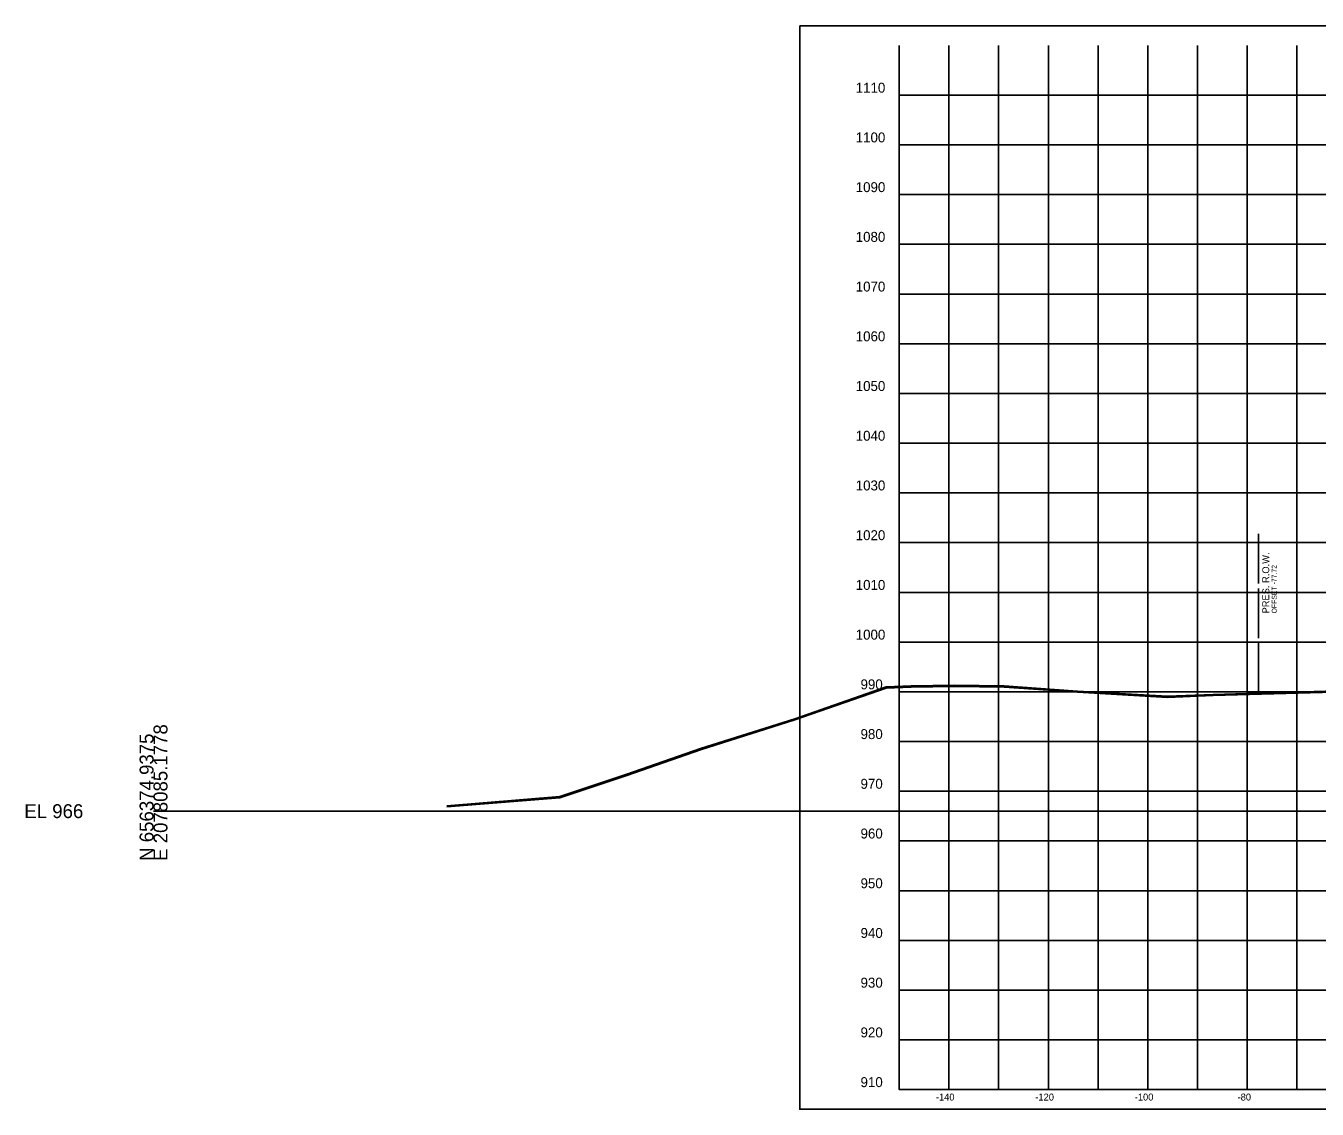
# Model space of a CAD drawing. Extents: x 5868 to 6683, y 2883 to 19120.
# Drawn here: x 5868.1 to 6127.9, y 14385.1 to 14603 of the extents above; entities that cross this region are included whole.
import ezdxf

# ---------------------------------------------------------------- set-up
doc = ezdxf.new("R2010")
doc.units = 0
for name, color, linetype in [('DESIGN - SHEET - Corner Text', 7, 'Continuous'), ('DESIGN - SHEET - Light Grid', 7, 'Continuous'), ('DESIGN - SHEET - Linework', 7, 'Continuous'), ('DESIGN - SHEET - Plot Shape', 7, 'Continuous'), ('SURVEY - GROUND - Bottom of Topsoil Layer', 7, 'Continuous'), ('SURVEY - GROUND - Top of Ground', 7, 'Continuous'), ('SURVEY - PROPERTY - ROW Lines', 7, 'Continuous'), ('SURVEY - PROPERTY - ROW Lines Text', 7, 'Continuous')]:
    doc.layers.add(name, color=color, linetype=linetype)

msp = doc.modelspace()

# ---------------------------------------------------------------- linework, layer by layer
at = {"layer": 'DESIGN - SHEET - Light Grid'}
msp.add_line((5893.78, 14445.07), (6193.78, 14445.07), dxfattribs=at)
at = {"layer": 'DESIGN - SHEET - Linework'}
for p, q in [((6053.78, 14389.07), (6053.78, 14599.07)), ((6063.78, 14389.07), (6063.78, 14599.07)), ((6073.78, 14389.07), (6073.78, 14599.07)), ((6083.78, 14389.07), (6083.78, 14599.07)), ((6093.78, 14389.07), (6093.78, 14599.07)), ((6103.78, 14389.07), (6103.78, 14599.07)), ((6113.78, 14389.07), (6113.78, 14599.07)), ((6123.78, 14389.07), (6123.78, 14599.07)), ((6043.78, 14589.07), (6343.78, 14589.07)), ((6043.78, 14579.07), (6343.78, 14579.07)), ((6043.78, 14569.07), (6343.78, 14569.07)), ((6043.78, 14559.07), (6343.78, 14559.07)), ((6043.78, 14549.07), (6343.78, 14549.07)), ((6043.78, 14539.07), (6343.78, 14539.07)), ((6043.78, 14529.07), (6343.78, 14529.07)), ((6043.78, 14519.07), (6343.78, 14519.07)), ((6043.78, 14509.07), (6343.78, 14509.07)), ((6043.78, 14499.07), (6343.78, 14499.07)), ((6043.78, 14489.07), (6343.78, 14489.07)), ((6043.78, 14479.07), (6343.78, 14479.07)), ((6043.78, 14469.07), (6343.78, 14469.07)), ((6043.78, 14459.07), (6343.78, 14459.07)), ((6043.78, 14449.07), (6343.78, 14449.07)), ((6043.78, 14439.07), (6343.78, 14439.07)), ((6043.78, 14429.07), (6343.78, 14429.07)), ((6043.78, 14419.07), (6343.78, 14419.07)), ((6043.78, 14409.07), (6343.78, 14409.07)), ((6043.78, 14399.07), (6343.78, 14399.07))]:
    msp.add_line(p, q, dxfattribs=at)
msp.add_lwpolyline([(6043.78, 14599.07), (6043.78, 14389.07), (6343.78, 14389.07), (6343.78, 14599.07)], dxfattribs=at)
at = {"layer": 'DESIGN - SHEET - Plot Shape'}
msp.add_lwpolyline([(6023.78, 14603.01), (6363.78, 14603.01), (6363.78, 14385.13), (6023.78, 14385.13)], close=True, dxfattribs=at)
at = {"layer": 'SURVEY - GROUND - Bottom of Topsoil Layer'}
for p, q in [((6022.8, 14463.42), (6041.12, 14469.83)), ((6041.12, 14469.83), (6046.15, 14470)), ((6046.15, 14470), (6054.91, 14470.17)), ((6054.91, 14470.17), (6064.89, 14470.03)), ((6064.89, 14470.03), (6079.67, 14468.98)), ((6079.67, 14468.98), (6097.73, 14467.92)), ((6106.93, 14468.31), (6134, 14469.1)), ((6097.73, 14467.92), (6106.93, 14468.31)), ((6003.83, 14457.4), (6022.8, 14463.42)), ((5989.01, 14452.23), (6003.83, 14457.4)), ((5975.51, 14447.75), (5989.01, 14452.23)), ((5952.78, 14445.91), (5975.51, 14447.75))]:
    msp.add_line(p, q, dxfattribs=at)
at = {"layer": 'SURVEY - GROUND - Top of Ground'}
msp.add_lwpolyline([(5952.78, 14446.16), (5975.51, 14448), (5989.01, 14452.48), (6003.83, 14457.65), (6022.8, 14463.67), (6041.12, 14470.08), (6046.15, 14470.25), (6054.91, 14470.42), (6064.89, 14470.28), (6079.67, 14469.23), (6097.73, 14468.17), (6106.93, 14468.56), (6134, 14469.35)], dxfattribs=at)
at = {"layer": 'SURVEY - PROPERTY - ROW Lines'}
for p, q in [((6116.06, 14490.83), (6116.06, 14500.83)), ((6116.06, 14479.83), (6116.06, 14489.83)), ((6116.06, 14468.83), (6116.06, 14478.83))]:
    msp.add_line(p, q, dxfattribs=at)

# ---------------------------------------------------------------- texts
at = {"layer": 'DESIGN - SHEET - Corner Text'}
for s, height, p in [('1110', 2, (6035.03, 14589.57)), ('1100', 2, (6035.03, 14579.57)), ('1090', 2, (6035.03, 14569.57)), ('1080', 2, (6035.03, 14559.57)), ('1070', 2, (6035.03, 14549.57)), ('1060', 2, (6035.03, 14539.57)), ('1050', 2, (6035.03, 14529.57)), ('1040', 2, (6035.03, 14519.57)), ('1030', 2, (6035.03, 14509.57)), ('1020', 2, (6035.03, 14499.57)), ('1010', 2, (6035.03, 14489.57)), ('1000', 2, (6035.03, 14479.57)), ('990', 2, (6036, 14469.57)), ('980', 2, (6036, 14459.57)), ('970', 2, (6036, 14449.57)), ('960', 2, (6036, 14439.57)), ('950', 2, (6036, 14429.57)), ('940', 2, (6036, 14419.57)), ('930', 2, (6036, 14409.57)), ('920', 2, (6036, 14399.57)), ('910', 2, (6036, 14389.57)), ('-140', 1.4, (6051.16, 14386.87)), ('-120', 1.4, (6071.16, 14386.87)), ('-100', 1.4, (6091.16, 14386.87)), ('-80', 1.4, (6111.84, 14386.87))]:
    msp.add_text(s, height=height, dxfattribs=at).set_placement(p)
at = {"layer": 'DESIGN - SHEET - Light Grid'}
for s, p in [('E 2078085.1778', (5896.58, 14435.07)), ('N 656374.9375', (5893.78, 14435.07))]:
    msp.add_text(s, height=2.8, rotation=90, dxfattribs=at).set_placement(p)
msp.add_text('EL 966', height=2.8, dxfattribs=at).set_placement((5867.78, 14443.67))
at = {"layer": 'SURVEY - PROPERTY - ROW Lines Text'}
for s, height, p in [('PRES. R.O.W.', 1.4, (6118.21, 14484.83)), ('OFFSET -77.72', 1, (6119.71, 14484.83))]:
    msp.add_text(s, height=height, rotation=90, dxfattribs=at).set_placement(p)

doc.saveas('drawing.dxf')
